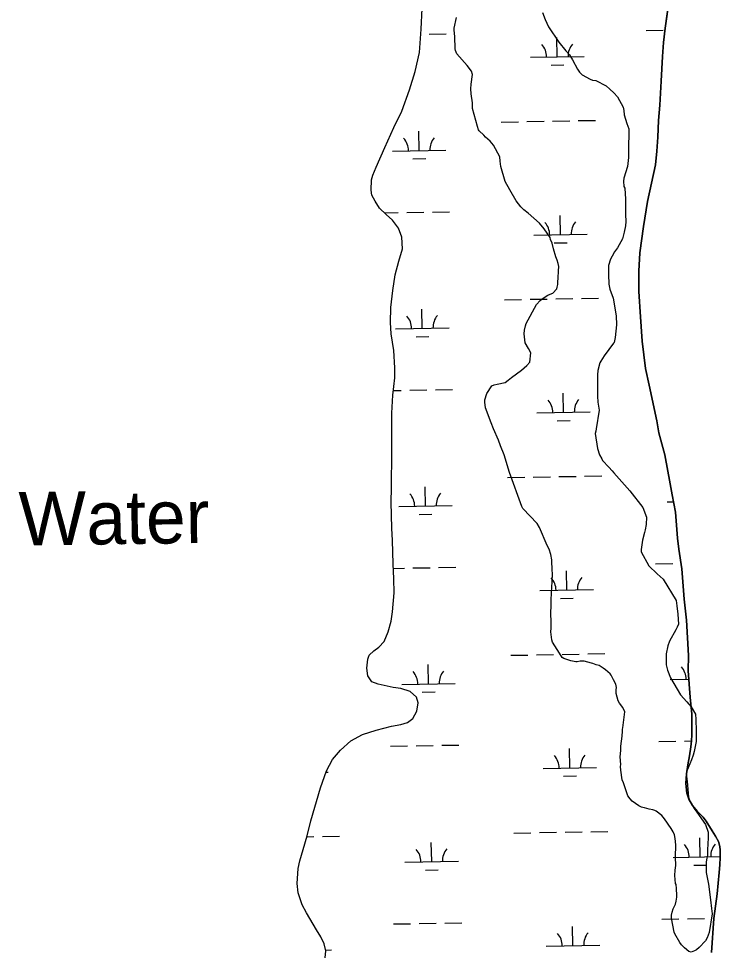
# Model space of a CAD drawing. Extents: x 3903937 to 3942190, y 260677 to 286651.
# Drawn here: x 3914480 to 3915792, y 266847 to 268594 of the extents above; entities that cross this region are included whole.
import ezdxf

# ---------------------------------------------------------------- set-up
doc = ezdxf.new("R2010")
doc.units = 0
for name, color, linetype in [('V-RIVR-IDEN', 7, 'Continuous'), ('V-SITE-VEGE', 7, 'Continuous'), ('V-TOPO-SHOR', 7, 'Continuous'), ('V-WETL-SWMP', 7, 'Continuous')]:
    doc.layers.add(name, color=color, linetype=linetype)

msp = doc.modelspace()

# ---------------------------------------------------------------- linework, layer by layer
at = {"layer": 'V-SITE-VEGE'}
for points in [[(3915459.6, 268605.2), (3915464.6, 268592.4), (3915470.7, 268578.6), (3915490.1, 268549.8), (3915503.3, 268533.9), (3915509.9, 268526.2), (3915514, 268520), (3915515.5, 268517), (3915525.2, 268499.5), (3915528.7, 268493.9), (3915533.8, 268488.7), (3915548.6, 268480.5), (3915553.2, 268478.9), (3915559.4, 268478.4), (3915578.8, 268468.1), (3915585.4, 268461.9), (3915593.1, 268455.2), (3915599.7, 268447.5), (3915610.4, 268428.5), (3915611.4, 268421.9), (3915612.3, 268413.7), (3915617.4, 268397.8), (3915620.9, 268387.6), (3915620.3, 268346.1), (3915620.2, 268333.8), (3915618.6, 268317.4), (3915611.9, 268295.5), (3915611.3, 268289.8), (3915611.8, 268280.1), (3915613.3, 268276.5), (3915614.8, 268256), (3915614.6, 268227.4), (3915615.1, 268214.1), (3915614.6, 268206.4), (3915612.5, 268194.1), (3915609.3, 268181.8), (3915599.5, 268165), (3915594.4, 268157.3), (3915589.8, 268149.7), (3915586.7, 268143.6), (3915583, 268131.8), (3915583, 268115.4), (3915583.4, 268097), (3915585.4, 268087.8), (3915591.5, 268070.9), (3915597.5, 268038.1), (3915597.9, 268021.2), (3915595.3, 267997.1), (3915593.7, 267987.9), (3915592.2, 267986.4), (3915574.7, 267962.9), (3915568.5, 267952.7), (3915566.9, 267949.7), (3915563.3, 267935.3), (3915562.2, 267927.7), (3915562.2, 267914.4), (3915562.6, 267887.7), (3915563, 267876), (3915565.5, 267861.1)], [(3915455.3, 268066.3), (3915458.9, 268069.4), (3915469.7, 268076.5), (3915476.9, 268079.5), (3915478.9, 268080.5), (3915486.1, 268088.2), (3915487.2, 268091.2), (3915488.2, 268096.4), (3915488.8, 268113.2), (3915489.3, 268117.3), (3915489.3, 268121.9), (3915489.9, 268130.1), (3915488.9, 268135.8), (3915486.9, 268141.9), (3915484.3, 268148.1), (3915479.8, 268162.9), (3915477.3, 268173.7), (3915474.7, 268180.9), (3915473.7, 268184.5), (3915462.5, 268200.9), (3915453.9, 268211.2), (3915432.4, 268229.7), (3915424.3, 268236.3), (3915419.2, 268241.5), (3915414.6, 268247.1), (3915410.5, 268253.3), (3915398.3, 268273.3), (3915389.7, 268289.2), (3915381.6, 268317.4), (3915380.1, 268327.1), (3915379.7, 268335.3), (3915368, 268356.9), (3915361.4, 268364.6), (3915353.2, 268372.3), (3915349.6, 268375.9), (3915341, 268384.1), (3915339.9, 268386.1), (3915337.9, 268391.8), (3915328.8, 268425.6), (3915328.4, 268436.4), (3915326.4, 268453.3), (3915325.4, 268462.5), (3915326, 268471.2), (3915328.6, 268489.6), (3915326.6, 268495.7), (3915318.9, 268506), (3915299.6, 268528.1), (3915296.5, 268534.2), (3915296, 268537.3), (3915295.6, 268560.3), (3915294.6, 268572.6), (3915294.1, 268576.2), (3915298.8, 268596.2)], [(3915682.7, 267102.6), (3915672, 267110.9), (3915669.4, 267112.4), (3915665.9, 267113.4), (3915658.7, 267114.5), (3915654.6, 267116.1), (3915650.5, 267117.1), (3915647.4, 267117.6), (3915644.9, 267118.7), (3915639.8, 267121.2), (3915627.5, 267129.5), (3915623.5, 267134.1), (3915619.4, 267139.7), (3915613.3, 267156.7), (3915610.8, 267164.3), (3915608.8, 267169.5), (3915605.8, 267187.9), (3915605.3, 267194.6), (3915605.8, 267198.1), (3915604.8, 267212.5), (3915605.9, 267224.8), (3915605.9, 267232.9), (3915608.6, 267251.4), (3915609.1, 267260.6), (3915609.1, 267264.2), (3915609.7, 267267.2), (3915613.4, 267296.9), (3915609.8, 267305.1), (3915603.7, 267312.8), (3915601.2, 267317.4), (3915597.1, 267331.3), (3915597.2, 267337.9), (3915597.7, 267342.5), (3915596.7, 267348.7), (3915592.6, 267356.9), (3915588.1, 267365.6), (3915586, 267368.2), (3915577.4, 267375.4), (3915572.8, 267378.4), (3915565.6, 267383.6), (3915560, 267385.1), (3915553.4, 267387.2), (3915551.3, 267387.7), (3915537.5, 267391.9), (3915529.8, 267391.4), (3915524.2, 267390.4), (3915522.1, 267390.4), (3915512.4, 267392), (3915499.1, 267396.7), (3915496.6, 267398.7), (3915491.5, 267406.4), (3915478.3, 267427.5), (3915476.8, 267431.6), (3915475.3, 267446.4), (3915475.8, 267453.6), (3915475.9, 267461.8), (3915475.4, 267484.3), (3915475.5, 267493), (3915476, 267496.6), (3915475.5, 267503.7), (3915476.1, 267521.1), (3915477.2, 267528.8), (3915478.3, 267553.9), (3915477.8, 267564.1), (3915476.9, 267577.9), (3915476.9, 267581), (3915475.4, 267591.2), (3915471.8, 267601), (3915468.3, 267608.2), (3915453.6, 267642), (3915449.5, 267649.2), (3915423, 267677.4), (3915421, 267681), (3915397.7, 267744.6), (3915387.6, 267777.9), (3915381, 267794.3), (3915377, 267805.1), (3915367.8, 267826.6), (3915363.8, 267837.9), (3915352.6, 267865.6), (3915351.7, 267876.3), (3915351.7, 267880.4), (3915355.3, 267892.7), (3915364.6, 267907), (3915369.2, 267909), (3915374.8, 267910), (3915389.7, 267913), (3915395.3, 267917.6), (3915401.5, 267922.2), (3915420.5, 267935.9), (3915430.2, 267944.6), (3915435.9, 267951.2), (3915437.5, 267968.6), (3915433.5, 267976.8), (3915426.8, 267987.6), (3915425.4, 268004), (3915425.9, 268011.1), (3915427.5, 268019.3), (3915429, 268023.4), (3915448.6, 268059.2), (3915455.3, 268066.3)], [(3915565.5, 267861.1), (3915559.8, 267826.3), (3915559.2, 267822.2), (3915558.2, 267817.6), (3915562.2, 267789.5), (3915566.2, 267777.7), (3915570.3, 267770.5), (3915571.8, 267766.9), (3915583.5, 267754.6), (3915589.6, 267747.9), (3915593.2, 267744.3), (3915622.8, 267710.4), (3915647.2, 267679.1), (3915654.3, 267661.1), (3915653.7, 267647.3), (3915651.6, 267637.6), (3915650.1, 267632.5), (3915646.4, 267618.2), (3915643.8, 267600.8), (3915643.8, 267596.2), (3915658.5, 267570), (3915673.8, 267555.1), (3915679.4, 267550), (3915685.5, 267545.3), (3915709.4, 267505.3), (3915710.9, 267495.1), (3915712.4, 267479.7), (3915713.9, 267460.8), (3915711.3, 267455.2), (3915708.7, 267450), (3915696.8, 267429.1), (3915694.2, 267420.4), (3915691.1, 267405.1), (3915691, 267384.6), (3915693, 267374.9), (3915698.6, 267360.5), (3915717.4, 267328.7), (3915729.6, 267315.4), (3915737.8, 267306.1), (3915745.4, 267292.3), (3915746.4, 267282.5), (3915746.4, 267276.9), (3915746.8, 267267.2), (3915746.7, 267241.6), (3915743.1, 267222.7), (3915741, 267215.5), (3915737.9, 267207.3), (3915728.6, 267184.3), (3915729.1, 267176.1), (3915730, 267166.4), (3915732.5, 267137.2), (3915735.5, 267128), (3915744.2, 267114.1), (3915748.2, 267109), (3915764.5, 267085.9), (3915769.1, 267071.6), (3915769.5, 267060.8), (3915767.9, 267038.8), (3915767.9, 267028.6), (3915766.3, 267019.9), (3915765.8, 267015.3), (3915765.7, 266996.3), (3915769.7, 266974.3), (3915773.7, 266945.1), (3915775.6, 266928.7), (3915777.1, 266919), (3915771.4, 266884.2), (3915767.2, 266874), (3915764.6, 266868.4), (3915752.3, 266855.6), (3915747.7, 266851.6), (3915744.1, 266849.5), (3915737.4, 266847), (3915733.3, 266848.6), (3915725.2, 266855.2), (3915719.6, 266860.9), (3915716.5, 266865), (3915706.9, 266881.4), (3915705.9, 266884.5), (3915700.8, 266910.6), (3915700.9, 266916.2), (3915701.9, 266921.9), (3915704, 266928), (3915708.1, 266936.7), (3915709.7, 266942.3), (3915710.7, 266950), (3915710.7, 266953.1), (3915710.3, 266966.4), (3915709.3, 266973.5), (3915708.3, 266975.6), (3915706.8, 266990.4), (3915707.9, 267000.7), (3915708.9, 267009.4), (3915708.5, 267024.7), (3915708.6, 267047.8), (3915707.6, 267060), (3915706.1, 267066.7), (3915703.6, 267072.3), (3915700, 267078.5), (3915687.8, 267096.5), (3915682.7, 267102.6)]]:
    msp.add_lwpolyline(points, dxfattribs=at)
at = {"layer": 'V-TOPO-SHOR'}
msp.add_lwpolyline([(3915775.4, 266846.7), (3915780.1, 266909.9), (3915786.3, 266956.1), (3915789.9, 266996), (3915791.1, 267010.8), (3915792.1, 267024.5), (3915792, 267037.8), (3915791.2, 267045), (3915788.5, 267054.3), (3915782.8, 267064.3), (3915776.9, 267074.4), (3915765.5, 267092.1), (3915759.8, 267099.7), (3915748.8, 267111), (3915740.1, 267121.4), (3915733.2, 267133.2), (3915729.4, 267144.4), (3915727.6, 267162.9), (3915729, 267181), (3915731.3, 267197.7), (3915734.5, 267214.4), (3915736.7, 267231.4), (3915738.1, 267242.6), (3915738.8, 267253.6), (3915738.6, 267292.8), (3915735.8, 267324.1), (3915731.8, 267373.8), (3915732.8, 267402), (3915728.8, 267468.5), (3915724.5, 267507.8), (3915720, 267564.3), (3915714.5, 267601.3), (3915712.3, 267621.8), (3915708.2, 267670.3), (3915701.9, 267703), (3915698.1, 267723.6), (3915688.3, 267777.9), (3915677.3, 267819.1), (3915673.5, 267841.6), (3915658.9, 267908.4), (3915652.2, 267939.2), (3915645.8, 267990.6), (3915642.5, 268035.9), (3915639.7, 268083.5), (3915639.4, 268121.7), (3915641.4, 268155.6), (3915648.3, 268205.2), (3915656, 268251.7), (3915670.6, 268320.6), (3915673.2, 268346.2), (3915675.3, 268372), (3915676.6, 268403.2), (3915678.8, 268432.2), (3915681.4, 268477.1), (3915684.1, 268523.1), (3915686.1, 268549.3), (3915688.9, 268575.9), (3915698.5, 268644.3)], dxfattribs=at)
at = {"layer": 'V-WETL-SWMP'}
for p, q in [((3915698.5, 268644.3), (3915688.9, 268575.9)), ((3915232.6, 268574.5), (3915234.4, 268613.1)), ((3915229.3, 268530.7), (3915232.6, 268574.5)), ((3915247.6, 268564.7), (3915279.6, 268565.3)), ((3915653.5, 268571.8), (3915685.4, 268572.4)), ((3915688.9, 268575.9), (3915686.1, 268549.3)), ((3915487.2, 268522.5), (3915486.6, 268558.5)), ((3915686.1, 268549.3), (3915684.1, 268523.1)), ((3915221.4, 268495.1), (3915229.3, 268530.7)), ((3915437.2, 268521.6), (3915537.2, 268523.3)), ((3915684.1, 268523.1), (3915681.4, 268477.1)), ((3915211, 268460.6), (3915221.4, 268495.1)), ((3915475.5, 268506.8), (3915499.5, 268507.3)), ((3915681.4, 268477.1), (3915678.8, 268432.2)), ((3915196.2, 268420.9), (3915211, 268460.6)), ((3915678.8, 268432.2), (3915676.6, 268403.2)), ((3915181.6, 268389.9), (3915196.2, 268420.9)), ((3915164.8, 268353.1), (3915181.6, 268389.9)), ((3915382.5, 268400.5), (3915414.5, 268401.1)), ((3915430.5, 268401.4), (3915462.5, 268401.9)), ((3915478.5, 268402.2), (3915510.5, 268402.8)), ((3915526.5, 268403.1), (3915558.5, 268403.6)), ((3915676.6, 268403.2), (3915675.3, 268372)), ((3915228.8, 268347.1), (3915228.2, 268383.1)), ((3915675.3, 268372), (3915673.2, 268346.2)), ((3915148.6, 268316.3), (3915164.8, 268353.1)), ((3915178.8, 268346.2), (3915278.8, 268348)), ((3915673.2, 268346.2), (3915670.6, 268320.6)), ((3915217.1, 268331.4), (3915241.1, 268331.9)), ((3915670.6, 268320.6), (3915656, 268251.7)), ((3915139.8, 268292.4), (3915142.2, 268301.1)), ((3915142.2, 268301.1), (3915148.6, 268316.3)), ((3915139.3, 268273.2), (3915139.8, 268292.4)), ((3915140.6, 268263.6), (3915139.3, 268273.2)), ((3915146.3, 268252.1), (3915140.6, 268263.6)), ((3915154.6, 268239.2), (3915146.3, 268252.1)), ((3915656, 268251.7), (3915648.3, 268205.2)), ((3915167.2, 268227.5), (3915154.6, 268239.2)), ((3915164, 268230.5), (3915189.5, 268230.9)), ((3915205.5, 268231.2), (3915237.5, 268231.8)), ((3915253.5, 268232.1), (3915285.5, 268232.6)), ((3915179.1, 268216.7), (3915167.2, 268227.5)), ((3915190.5, 268201.6), (3915179.1, 268216.7)), ((3915493.1, 268189.8), (3915492.5, 268225.8)), ((3915196.6, 268185), (3915190.5, 268201.6)), ((3915648.3, 268205.2), (3915641.4, 268155.6)), ((3915197.5, 268163.2), (3915196.6, 268185)), ((3915443.1, 268189), (3915543.1, 268190.7)), ((3915191, 268140.2), (3915197.5, 268163.2)), ((3915481.4, 268174.2), (3915505.4, 268174.6)), ((3915641.4, 268155.6), (3915639.4, 268121.7)), ((3915184, 268114.7), (3915191, 268140.2)), ((3915179.3, 268085.2), (3915184, 268114.7)), ((3915639.4, 268121.7), (3915639.7, 268083.5)), ((3915176, 268053.5), (3915179.3, 268085.2)), ((3915639.7, 268083.5), (3915642.5, 268035.9)), ((3915388.4, 268067.9), (3915420.4, 268068.5)), ((3915436.4, 268068.8), (3915468.4, 268069.3)), ((3915484.4, 268069.6), (3915516.4, 268070.2)), ((3915532.3, 268070.4), (3915564.3, 268071)), ((3915175.3, 268025.4), (3915176, 268053.5)), ((3915234.7, 268014.5), (3915234.1, 268050.5)), ((3915176.2, 268004.2), (3915175.3, 268025.4)), ((3915642.5, 268035.9), (3915645.8, 267990.6)), ((3915181.6, 267972.9), (3915176.2, 268004.2)), ((3915184.7, 268013.6), (3915284.7, 268015.3)), ((3915223, 267998.8), (3915247, 267999.2)), ((3915645.8, 267990.6), (3915652.2, 267939.2)), ((3915183.3, 267940.4), (3915181.6, 267972.9)), ((3915183.2, 267921.6), (3915183.3, 267940.4)), ((3915652.2, 267939.2), (3915658.9, 267908.4)), ((3915179.7, 267889.3), (3915183.2, 267921.6)), ((3915180.6, 267898.1), (3915195.3, 267898.3)), ((3915211.3, 267898.6), (3915243.3, 267899.2)), ((3915259.3, 267899.4), (3915291.3, 267900)), ((3915658.9, 267908.4), (3915673.5, 267841.6)), ((3915177.6, 267855.6), (3915179.7, 267889.3)), ((3915498.9, 267857.2), (3915498.3, 267893.2)), ((3915177.8, 267818.4), (3915177.6, 267855.6)), ((3915448.9, 267856.3), (3915548.9, 267858.1)), ((3915487.2, 267841.6), (3915511.2, 267842)), ((3915673.5, 267841.6), (3915677.3, 267819.1)), ((3915177.9, 267783.1), (3915177.8, 267818.4)), ((3915677.3, 267819.1), (3915688.3, 267777.9)), ((3915177.4, 267716.2), (3915177.9, 267783.1)), ((3915688.3, 267777.9), (3915698.1, 267723.6)), ((3915394.2, 267735.3), (3915426.2, 267735.9)), ((3915442.2, 267736.1), (3915474.2, 267736.7)), ((3915490.2, 267737), (3915522.2, 267737.5)), ((3915538.2, 267737.8), (3915570.2, 267738.4)), ((3915698.1, 267723.6), (3915701.9, 267703)), ((3915176.5, 267689.3), (3915177.4, 267716.2)), ((3915240.6, 267681.8), (3915239.9, 267717.8)), ((3915177.7, 267640.5), (3915176.5, 267689.3)), ((3915692.4, 267689.8), (3915704.4, 267690)), ((3915701.9, 267703), (3915708.2, 267670.3)), ((3915190.6, 267681), (3915290.5, 267682.7)), ((3915228.8, 267666.2), (3915252.8, 267666.6)), ((3915708.2, 267670.3), (3915712.3, 267621.8)), ((3915179.2, 267617.3), (3915177.7, 267640.5)), ((3915712.3, 267621.8), (3915714.5, 267601.3)), ((3915180.4, 267573.6), (3915179.2, 267617.3)), ((3915714.5, 267601.3), (3915720, 267564.3)), ((3915181.3, 267545.8), (3915180.4, 267573.6)), ((3915217.2, 267566), (3915249.2, 267566.5)), ((3915265.2, 267566.8), (3915297.2, 267567.4)), ((3915671, 267574), (3915703, 267574.5)), ((3915180.6, 267565.3), (3915201.2, 267565.7)), ((3915504.8, 267524.6), (3915504.2, 267560.6)), ((3915720, 267564.3), (3915724.5, 267507.8)), ((3915182.1, 267519.5), (3915181.3, 267545.8)), ((3915179, 267483.8), (3915182.1, 267519.5)), ((3915454.8, 267523.7), (3915554.8, 267525.5)), ((3915493.1, 267509), (3915517.1, 267509.4)), ((3915724.5, 267507.8), (3915728.8, 267468.5)), ((3915176.6, 267466.6), (3915179, 267483.8)), ((3915170.9, 267446.6), (3915176.6, 267466.6)), ((3915728.8, 267468.5), (3915732.8, 267402)), ((3915163.5, 267428.2), (3915170.9, 267446.6)), ((3915153.6, 267417.8), (3915163.5, 267428.2)), ((3915135.5, 267402.6), (3915144.3, 267410.9)), ((3915144.3, 267410.9), (3915153.6, 267417.8)), ((3915131, 267378.8), (3915132.7, 267395.1)), ((3915132.7, 267395.1), (3915135.5, 267402.6)), ((3915400.1, 267402.7), (3915432.1, 267403.2)), ((3915448.1, 267403.5), (3915480.1, 267404.1)), ((3915496.1, 267404.4), (3915528.1, 267404.9)), ((3915544.1, 267405.2), (3915576.1, 267405.8)), ((3915732.8, 267402), (3915731.8, 267373.8)), ((3915133, 267364.2), (3915131, 267378.8)), ((3915246.4, 267349.2), (3915245.8, 267385.2)), ((3915731.8, 267373.8), (3915735.8, 267324.1)), ((3915140.1, 267352.7), (3915133, 267364.2)), ((3915698.2, 267357.2), (3915733.1, 267357.8)), ((3915152.1, 267348.4), (3915140.1, 267352.7)), ((3915180.4, 267342.2), (3915152.1, 267348.4)), ((3915194.7, 267340.3), (3915180.4, 267342.2)), ((3915211.9, 267334.9), (3915194.7, 267340.3)), ((3915196.4, 267348.3), (3915296.4, 267350.1)), ((3915223.7, 267324), (3915211.9, 267334.9)), ((3915226.9, 267313.5), (3915223.7, 267324)), ((3915234.7, 267333.6), (3915258.7, 267334)), ((3915735.8, 267324.1), (3915738.6, 267292.8)), ((3915224.2, 267298.4), (3915226.9, 267313.5)), ((3915217, 267284.6), (3915224.2, 267298.4)), ((3915738.6, 267292.8), (3915738.8, 267253.6)), ((3915148.6, 267262.3), (3915177.2, 267269.9)), ((3915177.2, 267269.9), (3915194.4, 267273.2)), ((3915194.4, 267273.2), (3915207.1, 267277.1)), ((3915207.1, 267277.1), (3915217, 267284.6)), ((3915101, 267242.9), (3915123, 267254.7)), ((3915123, 267254.7), (3915148.6, 267262.3)), ((3915738.8, 267253.6), (3915738.1, 267242.6)), ((3915081.7, 267224.9), (3915101, 267242.9)), ((3915271, 267234.2), (3915303, 267234.8)), ((3915676.9, 267241.3), (3915708.9, 267241.9)), ((3915724.9, 267242.2), (3915738, 267242.4)), ((3915738.1, 267242.6), (3915736.7, 267231.4)), ((3915067, 267207.8), (3915081.7, 267224.9)), ((3915175, 267232.5), (3915207, 267233.1)), ((3915223, 267233.4), (3915255, 267233.9)), ((3915510.6, 267192), (3915510, 267228)), ((3915736.7, 267231.4), (3915734.5, 267214.4)), ((3915055.4, 267186.2), (3915067, 267207.8)), ((3915734.5, 267214.4), (3915731.3, 267197.7)), ((3915044.4, 267154.4), (3915055.4, 267186.2)), ((3915054.6, 267183.9), (3915058.8, 267184)), ((3915460.7, 267191.1), (3915560.6, 267192.9)), ((3915731.3, 267197.7), (3915729, 267181)), ((3915498.9, 267176.3), (3915522.9, 267176.8)), ((3915729, 267181), (3915727.6, 267162.9)), ((3915026.5, 267092.8), (3915044.4, 267154.4)), ((3915727.6, 267162.9), (3915729.4, 267144.4)), ((3915729.4, 267144.4), (3915733.2, 267133.2)), ((3915733.2, 267133.2), (3915740.1, 267121.4)), ((3915740.1, 267121.4), (3915748.8, 267111)), ((3915748.8, 267111), (3915759.8, 267099.7)), ((3915759.8, 267099.7), (3915765.5, 267092.1)), ((3915019.6, 267065.1), (3915026.5, 267092.8)), ((3915765.5, 267092.1), (3915776.9, 267074.4)), ((3915012, 267039), (3915019.6, 267065.1)), ((3915019.1, 267063.2), (3915032.1, 267063.5)), ((3915048.1, 267063.7), (3915080.1, 267064.3)), ((3915405.9, 267070), (3915437.9, 267070.6)), ((3915453.9, 267070.9), (3915485.9, 267071.5)), ((3915501.9, 267071.7), (3915533.9, 267072.3)), ((3915549.9, 267072.6), (3915581.9, 267073.1)), ((3915754.1, 267025.4), (3915753.5, 267061.4)), ((3915776.9, 267074.4), (3915782.8, 267064.3)), ((3915782.8, 267064.3), (3915788.5, 267054.3)), ((3915252.3, 267016.6), (3915251.6, 267052.6)), ((3915788.5, 267054.3), (3915791.2, 267045)), ((3915791.2, 267045), (3915792, 267037.8)), ((3915005.8, 267017.9), (3915012, 267039)), ((3915704.1, 267024.5), (3915792.1, 267026.1)), ((3915792.1, 267024.5), (3915791.1, 267010.8)), ((3915792, 267037.8), (3915792.1, 267024.5)), ((3915002.7, 267003.6), (3915005.8, 267017.9)), ((3915202.3, 267015.7), (3915302.3, 267017.5)), ((3915742.4, 267009.8), (3915766.4, 267010.2)), ((3915791.1, 267010.8), (3915789.9, 266996)), ((3915000.8, 266975.5), (3915002.7, 267003.6)), ((3915240.5, 267000.9), (3915264.5, 267001.4)), ((3915789.9, 266996), (3915786.3, 266956.1)), ((3915002.5, 266958), (3915000.8, 266975.5)), ((3915009.8, 266935.6), (3915002.5, 266958)), ((3915786.3, 266956.1), (3915780.1, 266909.9)), ((3915018, 266920.9), (3915009.8, 266935.6)), ((3915036.9, 266889), (3915018, 266920.9)), ((3915276.9, 266901.6), (3915308.9, 266902.1)), ((3915682.7, 266908.7), (3915714.7, 266909.3)), ((3915730.7, 266909.6), (3915762.7, 266910.1)), ((3915780.1, 266909.9), (3915775.4, 266846.7)), ((3915778.7, 266910.4), (3915780.2, 266910.4)), ((3915044.8, 266876.1), (3915036.9, 266889)), ((3915180.9, 266899.9), (3915212.9, 266900.4)), ((3915228.9, 266900.7), (3915260.9, 266901.3)), ((3915516.5, 266859.4), (3915515.9, 266895.3)), ((3915051.1, 266863), (3915044.8, 266876.1)), ((3915054.4, 266849.5), (3915051.1, 266863)), ((3915054, 266851.2), (3915064.7, 266851.4)), ((3915466.5, 266858.5), (3915566.5, 266860.2)), ((3915053.3, 266836.8), (3915054.4, 266849.5))]:
    msp.add_line(p, q, dxfattribs=at)
for centre, start, end in [((3915432, 268522), 0.2366, 41.7802), ((3915542.5, 268523.9), 140.2366, 181.7802), ((3915173.6, 268346.6), 0.2366, 41.7802), ((3915284.1, 268348.5), 140.2366, 181.7802), ((3915437.8, 268189.3), 0.2366, 41.7802), ((3915548.3, 268191.3), 140.2366, 181.7802), ((3915289.9, 268015.9), 140.2366, 181.7802), ((3915179.5, 268014), 0.2366, 41.7802), ((3915554.2, 267858.7), 140.2366, 181.7802), ((3915443.7, 267856.7), 0.2366, 41.7802), ((3915295.8, 267683.3), 140.2366, 181.7802), ((3915185.3, 267681.3), 0.2366, 41.7802), ((3915560, 267526), 140.2366, 181.7802), ((3915449.6, 267524.1), 0.2366, 41.7802), ((3915693, 267357.5), 0.2366, 41.7802), ((3915191.2, 267348.7), 0.2366, 41.7802), ((3915301.6, 267350.7), 140.2366, 181.7802), ((3915455.4, 267191.5), 0.2366, 41.7802), ((3915565.9, 267193.4), 140.2366, 181.7802), ((3915698.8, 267024.9), 0.2366, 41.7802), ((3915809.3, 267026.9), 140.2366, 181.7802), ((3915197, 267016.1), 0.2366, 41.7802), ((3915307.5, 267018), 140.2366, 181.7802), ((3915461.3, 266858.9), 0.2366, 41.7802), ((3915571.7, 266860.8), 140.2366, 181.7802)]:
    msp.add_arc(centre, 35.2, start, end, dxfattribs=at)

# ---------------------------------------------------------------- texts
at = {"layer": 'V-RIVR-IDEN'}
msp.add_text('Water', height=100, rotation=0.8107, dxfattribs=at).set_placement((3914480.7, 267607.9))

doc.saveas('drawing.dxf')
